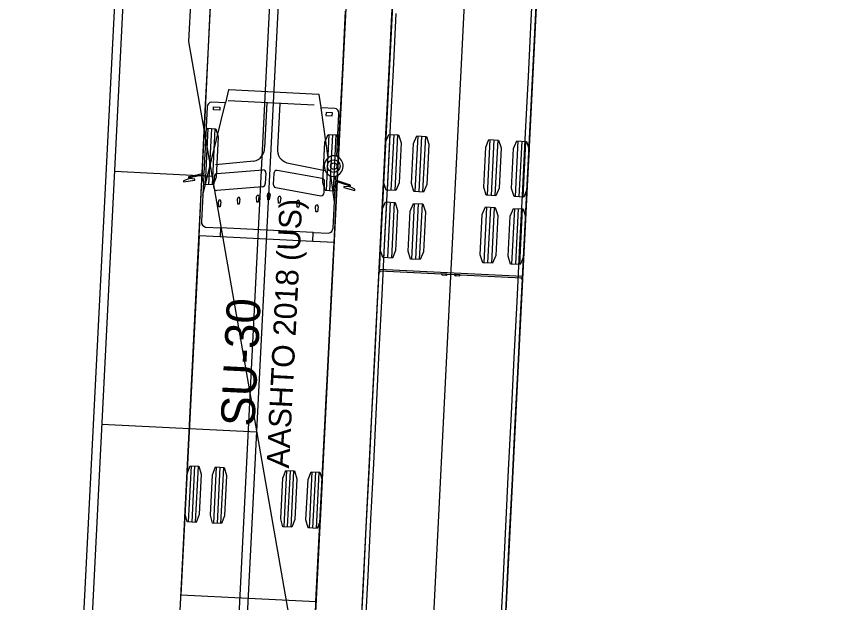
# Model space of a CAD drawing. Extents: x 260275 to 261282, y 610916 to 614143.
# Drawn here: x 261035.25 to 261084.25, y 612155.03 to 612189.71 of the extents above; entities that cross this region are included whole.
import ezdxf

# ---------------------------------------------------------------- set-up
doc = ezdxf.new("R2010")
doc.units = 0
for name, color, linetype in [('GE_X_Alignment', 7, 'Continuous'), ('PV_P_Curb', 7, 'Continuous'), ('PV_P_EOP', 7, 'Continuous'), ('PV_P_Joint', 7, 'Continuous'), ('TopoDOT_Transients', 7, 'Continuous')]:
    doc.layers.add(name, color=color, linetype=linetype)

msp = doc.modelspace()

# ---------------------------------------------------------------- linework, layer by layer
at = {"layer": 'GE_X_Alignment'}
msp.add_line((260986.249, 610915.954), (261148.276, 614142.838), dxfattribs=at)
at = {"layer": 'PV_P_Curb'}
msp.add_line((261041.82, 612206.041), (261037.345, 612116.921), dxfattribs=at)
at = {"layer": 'PV_P_EOP'}
for p, q in [((261046.541, 612210.324), (261045.432, 612188.236)), ((261042.321, 612206.054), (261037.849, 612116.977)), ((261045.432, 612188.236), (261059.122, 612109.815))]:
    msp.add_line(p, q, dxfattribs=at)
at = {"layer": 'PV_P_Joint'}
for p, q in [((261041.041, 612180.562), (261046.822, 612180.272)), ((261040.289, 612165.581), (261049.467, 612165.12))]:
    msp.add_line(p, q, dxfattribs=at)
at = {"layer": 'TopoDOT_Transients'}
for p, q in [((261059.045, 612136.423), (261081.046, 612574.591)), ((261048.059, 612136.974), (261068.197, 612538.052)), ((261052.866, 612184.462), (261047.767, 612184.718)), ((261046.271, 612179.135), (261047.611, 612184.602)), ((261046.9, 612184.182), (261046.91, 612184.376)), ((261047.278, 612184.163), (261046.9, 612184.182)), ((261046.91, 612184.376), (261047.288, 612184.357)), ((261047.288, 612184.357), (261047.278, 612184.163)), ((261050.067, 612184.602), (261049.933, 612181.937)), ((261050.832, 612184.564), (261050.698, 612181.899)), ((261053.693, 612181.352), (261053.275, 612184.318)), ((261053.572, 612184.041), (261053.562, 612183.847)), ((261053.562, 612183.847), (261053.94, 612183.828)), ((261053.95, 612184.022), (261053.572, 612184.041)), ((261053.94, 612183.828), (261053.95, 612184.022)), ((261054.197, 612181.443), (261054.323, 612183.962)), ((261046.578, 612183.097), (261046.411, 612179.768)), ((261046.786, 612183.087), (261046.619, 612179.758)), ((261046.994, 612183.076), (261046.827, 612179.747)), ((261053.736, 612182.738), (261053.569, 612179.409)), ((261053.944, 612182.727), (261053.777, 612179.398)), ((261054.152, 612182.717), (261053.985, 612179.388)), ((261057.344, 612182.729), (261057.179, 612179.433)), ((261057.573, 612182.717), (261057.407, 612179.421)), ((261057.802, 612182.706), (261057.636, 612179.41)), ((261058.992, 612182.646), (261058.827, 612179.35)), ((261059.221, 612182.634), (261059.055, 612179.338)), ((261059.45, 612182.623), (261059.284, 612179.327)), ((261063.27, 612182.431), (261063.104, 612179.135)), ((261063.499, 612182.42), (261063.333, 612179.124)), ((261063.728, 612182.408), (261063.562, 612179.112)), ((261064.918, 612182.348), (261064.752, 612179.052)), ((261065.147, 612182.337), (261064.981, 612179.041)), ((261065.376, 612182.325), (261065.21, 612179.029)), ((261049.295, 612181.161), (261047.016, 612180.93)), ((261051.255, 612181.063), (261053.511, 612180.602)), ((261046.931, 612179.621), (261046.962, 612180.237)), ((261047.123, 612180.431), (261049.832, 612180.647)), ((261050.003, 612180.437), (261049.972, 612179.821)), ((261050.478, 612180.413), (261050.447, 612179.797)), ((261053.343, 612180.119), (261050.669, 612180.605)), ((261054.061, 612178.744), (261053.845, 612180.277)), ((261053.453, 612179.294), (261053.484, 612179.91)), ((261049.81, 612179.626), (261047.102, 612179.41)), ((261050.588, 612179.587), (261053.262, 612179.101)), ((261047.214, 612178.451), (261047.193, 612178.752)), ((261047.347, 612178.744), (261047.296, 612178.447)), ((261048.34, 612178.605), (261048.319, 612178.92)), ((261048.473, 612178.912), (261048.423, 612178.601)), ((261049.465, 612178.731), (261049.444, 612179.032)), ((261049.598, 612179.025), (261049.547, 612178.727)), ((261050.121, 612178.867), (261050.1, 612179.168)), ((261050.203, 612178.863), (261050.121, 612178.867)), ((261050.254, 612179.16), (261050.203, 612178.863)), ((261050.76, 612178.666), (261050.739, 612178.967)), ((261050.893, 612178.96), (261050.842, 612178.662)), ((261057.144, 612178.734), (261056.978, 612175.438)), ((261047.296, 612178.447), (261047.214, 612178.451)), ((261048.423, 612178.601), (261048.34, 612178.605)), ((261049.547, 612178.727), (261049.465, 612178.731)), ((261050.842, 612178.662), (261050.76, 612178.666)), ((261051.867, 612178.428), (261051.846, 612178.729)), ((261051.949, 612178.424), (261051.867, 612178.428)), ((261052, 612178.721), (261051.949, 612178.424)), ((261052.972, 612178.162), (261052.951, 612178.463)), ((261053.105, 612178.455), (261053.054, 612178.158)), ((261057.372, 612178.722), (261057.207, 612175.426)), ((261057.601, 612178.711), (261057.436, 612175.415)), ((261058.791, 612178.651), (261058.626, 612175.355)), ((261059.02, 612178.639), (261058.855, 612175.344)), ((261059.249, 612178.628), (261059.084, 612175.332)), ((261063.069, 612178.436), (261062.904, 612175.14)), ((261063.298, 612178.425), (261063.133, 612175.129)), ((261063.527, 612178.413), (261063.362, 612175.117)), ((261064.717, 612178.353), (261064.552, 612175.057)), ((261064.946, 612178.342), (261064.781, 612175.046)), ((261065.175, 612178.33), (261065.01, 612175.034)), ((261053.054, 612178.158), (261052.972, 612178.162)), ((261052.814, 612176.928), (261047.329, 612177.204)), ((261052.788, 612176.397), (261047.303, 612176.673)), ((261065.203, 612174.315), (261056.714, 612174.741)), ((261060.689, 612174.471), (261060.424, 612174.484)), ((261060.695, 612174.471), (261061.218, 612174.444)), ((261060.955, 612174.458), (261060.958, 612174.528)), ((261061.485, 612174.431), (261061.22, 612174.444)), ((261045.575, 612163.122), (261045.408, 612159.793)), ((261045.783, 612163.112), (261045.616, 612159.783)), ((261045.991, 612163.101), (261045.824, 612159.772)), ((261047.073, 612163.047), (261046.906, 612159.718)), ((261047.281, 612163.037), (261047.114, 612159.708)), ((261047.489, 612163.026), (261047.322, 612159.697)), ((261051.235, 612162.838), (261051.068, 612159.509)), ((261051.443, 612162.828), (261051.276, 612159.499)), ((261051.651, 612162.817), (261051.484, 612159.488)), ((261052.733, 612162.763), (261052.566, 612159.434)), ((261052.941, 612162.752), (261052.774, 612159.423)), ((261053.149, 612162.742), (261052.982, 612159.413))]:
    msp.add_line(p, q, dxfattribs=at)
for points in [[(261051.548, 612071.863), (261074.206, 612523.277)], [(261082.631, 612521.243), (261060.03, 612071.291)], [(261042.767, 612111.356), (261063.016, 612514.614)], [(261070.923, 612512.551), (261050.75, 612110.806), (261042.76, 612111.207), (261042.767, 612111.356), (261042.767, 612111.356)], [(261065.177, 612174.246), (261065.199, 612174.245), (261067.603, 612222.114), (261063.358, 612222.327), (261059.114, 612222.54), (261056.71, 612174.671), (261056.732, 612174.67)], [(261055.611, 612152.791), (261055.779, 612156.121), (261055.946, 612159.45), (261056.113, 612162.78), (261056.28, 612166.109), (261056.447, 612169.439), (261056.615, 612172.769), (261056.782, 612176.098), (261056.949, 612179.428), (261057.116, 612182.757), (261057.283, 612186.087), (261057.45, 612189.416), (261057.618, 612192.746)], [(261063.876, 612152.87), (261064.043, 612156.199), (261064.21, 612159.529), (261064.377, 612162.858), (261064.545, 612166.188), (261064.712, 612169.517), (261064.879, 612172.847), (261065.046, 612176.176), (261065.213, 612179.506), (261065.38, 612182.836), (261065.548, 612186.165), (261065.715, 612189.495), (261065.882, 612192.824)], [(261064.101, 612152.365), (261064.268, 612155.695), (261064.435, 612159.024), (261064.602, 612162.354), (261064.769, 612165.683), (261064.937, 612169.013), (261065.104, 612172.342), (261065.271, 612175.672), (261065.438, 612179.001), (261065.605, 612182.331), (261065.773, 612185.66), (261065.94, 612188.99), (261066.107, 612192.32)], [(261044.899, 612153.817), (261045.067, 612157.145), (261045.234, 612160.474), (261045.401, 612163.802), (261045.568, 612167.131), (261045.735, 612170.459), (261045.902, 612173.788), (261046.069, 612177.116), (261046.236, 612180.445), (261046.404, 612183.773), (261046.571, 612187.101), (261046.738, 612190.43)], [(261044.899, 612153.813), (261045.066, 612157.141), (261045.233, 612160.47), (261045.401, 612163.798), (261045.568, 612167.127), (261045.735, 612170.455), (261045.902, 612173.783), (261046.069, 612177.112), (261046.236, 612180.44), (261046.403, 612183.769), (261046.57, 612187.097), (261046.738, 612190.426)], [(261052.889, 612153.416), (261053.056, 612156.744), (261053.224, 612160.073), (261053.391, 612163.401), (261053.558, 612166.73), (261053.725, 612170.058), (261053.892, 612173.386), (261054.059, 612176.715), (261054.226, 612180.043), (261054.393, 612183.372), (261054.561, 612186.7), (261054.728, 612190.029)], [(261052.889, 612153.412), (261053.056, 612156.74), (261053.223, 612160.068), (261053.391, 612163.397), (261053.558, 612166.725), (261053.725, 612170.054), (261053.892, 612173.382), (261054.059, 612176.711), (261054.226, 612180.039), (261054.393, 612183.368), (261054.56, 612186.696), (261054.728, 612190.025)], [(261055.886, 612153.271), (261056.053, 612156.6), (261056.22, 612159.93), (261056.387, 612163.259), (261056.555, 612166.589), (261056.722, 612169.919), (261056.889, 612173.248), (261057.056, 612176.578), (261057.223, 612179.907), (261057.39, 612183.237), (261057.558, 612186.566), (261057.725, 612189.896)], [(261054.085, 612184.277), (261053.278, 612184.318), (261053.274, 612184.323), (261053.164, 612185.101), (261053.122, 612185.105), (261050.482, 612185.237), (261047.842, 612185.37), (261047.8, 612185.37), (261047.613, 612184.607), (261047.608, 612184.603), (261046.801, 612184.643)], [(261046.533, 612184.353), (261046.336, 612180.425), (261046.328, 612180.414), (261045.486, 612180.229), (261045.485, 612180.229)], [(261045.5, 612180.181), (261045.5, 612180.181), (261046.328, 612180.359), (261046.332, 612180.347), (261046.193, 612177.577)], [(261054.952, 612179.754), (261054.951, 612179.754), (261054.132, 612180.022), (261054.126, 612180.034), (261054.137, 612180.262)], [(261045.441, 612180.158), (261045.438, 612180.111), (261045.438, 612180.111), (261045.137, 612179.994), (261045.134, 612179.929), (261045.136, 612179.929), (261045.799, 612180.035), (261045.802, 612180.036), (261045.804, 612180.092), (261045.802, 612180.092), (261045.485, 612180.117), (261045.485, 612180.117), (261045.488, 612180.161)], [(261053.983, 612177.185), (261054.122, 612179.956), (261054.127, 612179.968), (261054.932, 612179.707), (261054.933, 612179.707)], [(261054.943, 612179.687), (261054.941, 612179.642), (261054.941, 612179.642), (261054.623, 612179.649), (261054.621, 612179.649), (261054.618, 612179.594), (261054.621, 612179.592), (261055.269, 612179.42), (261055.272, 612179.42), (261055.275, 612179.485), (261054.987, 612179.631), (261054.987, 612179.632), (261054.989, 612179.679)], [(261046.431, 612177.249), (261047.326, 612177.204), (261047.329, 612177.2), (261047.303, 612176.674), (261047.292, 612176.673), (261046.05, 612176.736), (261044.983, 612155.476), (261048.978, 612155.275), (261052.973, 612155.075), (261054.04, 612176.334), (261052.799, 612176.397), (261052.788, 612176.398), (261052.814, 612176.924), (261052.817, 612176.928), (261053.712, 612176.883)], [(261056.757, 612174.668), (261056.757, 612174.668), (261060.388, 612174.486), (261060.424, 612174.484), (261060.421, 612174.414), (261060.422, 612174.414), (261060.688, 612174.4)], [(261061.214, 612174.374), (261061.48, 612174.361), (261061.482, 612174.361), (261061.485, 612174.431), (261061.521, 612174.429), (261065.152, 612174.247), (261065.153, 612174.247)]]:
    msp.add_lwpolyline(points, dxfattribs=at)
for points in [[(261046.527, 612183.1), (261047.046, 612183.074), (261047.179, 612182.6), (261047.059, 612180.203), (261046.879, 612179.745), (261046.359, 612179.771), (261046.226, 612180.245), (261046.347, 612182.642)], [(261053.684, 612182.74), (261054.204, 612182.714), (261054.337, 612182.24), (261054.216, 612179.843), (261054.036, 612179.385), (261053.517, 612179.411), (261053.384, 612179.885), (261053.504, 612182.282)], [(261057.287, 612182.731), (261057.859, 612182.703), (261058.008, 612182.233), (261057.888, 612179.86), (261057.693, 612179.407), (261057.122, 612179.436), (261056.973, 612179.906), (261057.092, 612182.279)], [(261058.935, 612182.649), (261059.507, 612182.62), (261059.655, 612182.15), (261059.536, 612179.777), (261059.341, 612179.324), (261058.77, 612179.353), (261058.621, 612179.823), (261058.74, 612182.196)], [(261063.213, 612182.434), (261063.784, 612182.405), (261063.933, 612181.935), (261063.814, 612179.562), (261063.619, 612179.109), (261063.048, 612179.138), (261062.899, 612179.608), (261063.018, 612181.981)], [(261064.861, 612182.351), (261065.432, 612182.322), (261065.581, 612181.852), (261065.462, 612179.479), (261065.267, 612179.027), (261064.696, 612179.055), (261064.547, 612179.525), (261064.666, 612181.898)], [(261057.087, 612178.736), (261057.658, 612178.708), (261057.807, 612178.238), (261057.688, 612175.865), (261057.493, 612175.412), (261056.921, 612175.441), (261056.772, 612175.911), (261056.891, 612178.284)], [(261058.735, 612178.654), (261059.306, 612178.625), (261059.455, 612178.155), (261059.336, 612175.782), (261059.14, 612175.329), (261058.569, 612175.358), (261058.42, 612175.828), (261058.539, 612178.201)], [(261063.013, 612178.439), (261063.584, 612178.41), (261063.733, 612177.94), (261063.614, 612175.567), (261063.418, 612175.114), (261062.847, 612175.143), (261062.698, 612175.613), (261062.817, 612177.986)], [(261064.661, 612178.356), (261065.232, 612178.327), (261065.381, 612177.857), (261065.262, 612175.484), (261065.066, 612175.032), (261064.495, 612175.06), (261064.346, 612175.53), (261064.465, 612177.903)], [(261045.524, 612163.125), (261046.043, 612163.099), (261046.176, 612162.625), (261046.056, 612160.228), (261045.876, 612159.77), (261045.356, 612159.796), (261045.223, 612160.27), (261045.344, 612162.667)], [(261047.022, 612163.05), (261047.541, 612163.024), (261047.674, 612162.55), (261047.554, 612160.153), (261047.374, 612159.694), (261046.855, 612159.721), (261046.722, 612160.195), (261046.842, 612162.591)], [(261051.183, 612162.841), (261051.703, 612162.815), (261051.836, 612162.341), (261051.715, 612159.944), (261051.535, 612159.486), (261051.016, 612159.512), (261050.883, 612159.986), (261051.003, 612162.383)], [(261052.681, 612162.766), (261053.201, 612162.739), (261053.334, 612162.266), (261053.213, 612159.869), (261053.033, 612159.41), (261052.514, 612159.436), (261052.381, 612159.91), (261052.501, 612162.307)]]:
    msp.add_lwpolyline(points, close=True, dxfattribs=at)
for centre, radius in [((261054.022, 612180.86), 0.374), ((261054.022, 612180.86), 0.193), ((261056.743, 612174.635), 0.0266), ((261065.163, 612174.212), 0.0266)]:
    msp.add_circle(centre, radius, dxfattribs=at)
for centre, radius, start, end in [((261046.814, 612184.362), 0.282, 92.6739, 181.7533), ((261054.044, 612183.999), 0.282, 352.4977, 81.5771), ((261049.16, 612181.923), 0.773, 280.016, 1.1001), ((261051.465, 612181.807), 0.773, 173.1509, 254.235), ((261054.091, 612180.864), 0.629, 129.1711, 177.8604), ((261054.026, 612180.946), 0.526, 71.0707, 129.3167), ((261053.955, 612180.863), 0.628, 286.8788, 67.3705), ((261054.09, 612180.849), 0.63, 176.4803, 228.8831), ((261045.464, 612180.193), 0.0418, 59.6174, 236.6324), ((261047.154, 612180.241), 0.193, 99.2679, 181.1824), ((261049.821, 612180.463), 0.184, 351.6672, 86.5274), ((261050.662, 612180.421), 0.184, 87.7236, 182.5838), ((261054.018, 612180.773), 0.524, 229.3845, 283.1846), ((261045.458, 612180.193), 0.0434, 312.5392, 343.212), ((261049.779, 612179.817), 0.193, 279.263, 1.1873), ((261050.638, 612179.773), 0.193, 173.0637, 254.988), ((261053.293, 612179.933), 0.193, 353.0686, 74.9831), ((261054.969, 612179.716), 0.0418, 297.6187, 114.6336), ((261047.113, 612179.595), 0.184, 171.6617, 266.5329), ((261050.19, 612179.182), 0.091, 94.6451, 188.8089), ((261050.166, 612179.183), 0.091, 345.4421, 79.6059), ((261053.269, 612179.285), 0.184, 267.7181, 2.5893), ((261054.975, 612179.716), 0.0434, 191.039, 221.7118), ((261047.283, 612178.766), 0.091, 94.6451, 188.8089), ((261047.259, 612178.767), 0.0909, 345.4064, 79.6416), ((261048.409, 612178.92), 0.091, 94.6451, 188.8089), ((261048.385, 612178.921), 0.0909, 345.4064, 79.6416), ((261049.534, 612179.046), 0.091, 94.6451, 188.8089), ((261049.51, 612179.047), 0.0909, 345.4064, 79.6416), ((261050.829, 612178.981), 0.0909, 94.6094, 188.8446), ((261050.805, 612178.982), 0.091, 345.4421, 79.6059), ((261051.936, 612178.743), 0.0909, 94.6094, 188.8446), ((261051.912, 612178.744), 0.091, 345.4421, 79.6059), ((261053.041, 612178.477), 0.0909, 94.6094, 188.8446), ((261053.017, 612178.478), 0.091, 345.4421, 79.6059), ((261046.515, 612177.56), 0.323, 177.1255, 254.9739), ((261053.66, 612177.202), 0.323, 279.2771, 357.1255), ((261056.743, 612174.635), 0.0363, 106.2023, 67.3649), ((261060.69, 612174.436), 0.0352, 86.913, 269.5524), ((261060.69, 612174.436), 0.0352, 267.1411, 87.7276), ((261061.216, 612174.409), 0.0352, 86.5234, 267.1099), ((261061.216, 612174.409), 0.0354, 271.417, 83.6025), ((261065.163, 612174.212), 0.0363, 106.8861, 68.0487)]:
    msp.add_arc(centre, radius, start, end, dxfattribs=at)

# ---------------------------------------------------------------- texts
for s, height, p in [('AASHTO 2018 (US)', 1.33333, (261051.372, 612162.95)), ('SU-30', 2, (261049.327, 612165.413))]:
    msp.add_text(s, height=height, rotation=87.1255, dxfattribs=at).set_placement(p)

doc.saveas('drawing.dxf')
